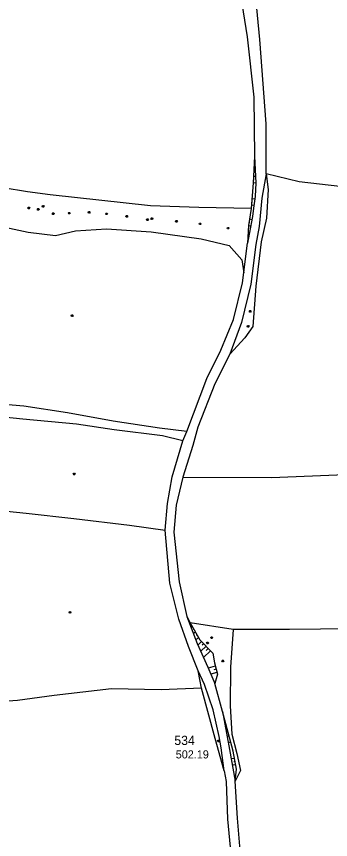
# Model space of a CAD drawing. Extents: x -664960 to -662754, y -993849 to -991145.
# Drawn here: x -663568.6 to -663452.1, y -992520.3 to -992215.3 of the extents above; entities that cross this region are included whole.
import ezdxf

# ---------------------------------------------------------------- set-up
doc = ezdxf.new("R2010")
doc.units = 0
for name, color, linetype in [('Vrstva 1', 7, 'Continuous'), ('Vrstva 13', 7, 'Continuous'), ('Vrstva 27', 7, 'Continuous'), ('Vrstva 63', 7, 'Continuous'), ('Vrstva 8', 7, 'Continuous')]:
    doc.layers.add(name, color=color, linetype=linetype)

msp = doc.modelspace()

# ---------------------------------------------------------------- linework, layer by layer
at = {"layer": 'Vrstva 13'}
for points in [[(-663481.752, -992324.262), (-663481.572, -992324.562), (-663481.752, -992324.862), (-663482.112, -992324.862), (-663482.292, -992324.562), (-663482.112, -992324.262), (-663481.752, -992324.262)], [(-663547.78, -992325.87), (-663547.6, -992326.17), (-663547.78, -992326.47), (-663548.14, -992326.47), (-663548.32, -992326.17), (-663548.14, -992325.87), (-663547.78, -992325.87)], [(-663547.013, -992384.574), (-663546.833, -992384.874), (-663547.013, -992385.174), (-663547.373, -992385.174), (-663547.553, -992384.874), (-663547.373, -992384.574), (-663547.013, -992384.574)], [(-663548.547, -992435.806), (-663548.367, -992436.106), (-663548.547, -992436.406), (-663548.907, -992436.406), (-663549.087, -992436.106), (-663548.907, -992435.806), (-663548.547, -992435.806)], [(-663491.887, -992453.848), (-663491.707, -992454.148), (-663491.887, -992454.448), (-663492.247, -992454.448), (-663492.427, -992454.148), (-663492.247, -992453.848), (-663491.887, -992453.848)]]:
    msp.add_lwpolyline(points, dxfattribs=at)
at = {"layer": 'Vrstva 27'}
for p, q in [((-663498.82, -992462.9), (-663498.82, -992462.9)), ((-663492.21, -992472.91), (-663495.09, -992462.49))]:
    msp.add_line(p, q, dxfattribs=at)
for points in [[(-663475.97, -992273.64), (-663477.58, -992282.65), (-663478.54, -992293.08), (-663479.81, -992299.82), (-663481.67, -992314.53), (-663485.12, -992328.72), (-663489.53, -992340.42), (-663495.04, -992351.42), (-663501.28, -992367.55), (-663503.19, -992374.27), (-663506.96, -992386.03), (-663509.35, -992396.38), (-663510.29, -992406.44), (-663508.31, -992424.82), (-663505.42, -992437.71)], [(-663513.46, -992405.65), (-663512.64, -992395.77), (-663510.85, -992385.96), (-663506.9, -992372.53), (-663505.4, -992369.12), (-663497.96, -992349.47), (-663492.81, -992339.02), (-663488.15, -992327.64), (-663484.78, -992313.98), (-663482.94, -992299.37)], [(-663491.56, -992494.88), (-663492.7, -992486.31), (-663493.48, -992482.18), (-663495.69, -992472.21), (-663498.82, -992462.9), (-663501.24, -992457.75), (-663504.79, -992448.84), (-663508.37, -992438.66), (-663511.74, -992425.37), (-663513.46, -992405.65)], [(-663491.56, -992494.88), (-663490.88, -992498.85), (-663490.29, -992512.79), (-663488.02, -992537.43), (-663486.54, -992563.07), (-663484.58, -992588.12), (-663484.13, -992607.11), (-663484.46, -992622.09), (-663487.97, -992643.83), (-663491.41, -992664.81), (-663493.48, -992685.99), (-663493.6, -992696.61), (-663493.51, -992707.44), (-663493.24, -992730.03), (-663493.3, -992747.16)], [(-663490.38, -992757.18), (-663489.72, -992746.74), (-663489.45, -992730.95), (-663490.22, -992707.23), (-663490.33, -992697.21), (-663489.9, -992685.74), (-663487.82, -992665.56), (-663484.63, -992643.86), (-663480.98, -992622.66), (-663480.17, -992606.94), (-663480.82, -992588.29), (-663482.91, -992562.68), (-663484.55, -992537.62), (-663486.62, -992512.45), (-663487.48, -992498.66)]]:
    msp.add_lwpolyline(points, dxfattribs=at)
at = {"layer": 'Vrstva 63'}
for p, q in [((-663480.569, -992272.068), (-663480.098, -992272.093)), ((-663480.508, -992270.87), (-663480.39, -992270.876)), ((-663480.446, -992269.672), (-663480.207, -992269.684)), ((-663480.692, -992274.465), (-663479.989, -992274.501)), ((-663480.63, -992273.267), (-663480.435, -992273.277)), ((-663480.814, -992276.862), (-663479.88, -992276.91)), ((-663480.753, -992275.664), (-663480.481, -992275.678)), ((-663481.328, -992283.959), (-663481.029, -992283.981)), ((-663481.241, -992282.762), (-663480.262, -992282.833)), ((-663481.415, -992285.156), (-663480.598, -992285.215)), ((-663482.194, -992290.356), (-663481.225, -992290.527)), ((-663482.61, -992292.72), (-663481.682, -992292.883)), ((-663482.402, -992291.538), (-663482.086, -992291.594)), ((-663503.378, -992441.444), (-663503.865, -992441.723)), ((-663502.781, -992442.485), (-663502.996, -992442.608)), ((-663502.185, -992443.526), (-663502.988, -992443.987)), ((-663500.991, -992445.608), (-663502.112, -992446.25)), ((-663501.588, -992444.567), (-663501.908, -992444.751)), ((-663499.966, -992446.941), (-663501.305, -992448.246)), ((-663498.291, -992448.66), (-663500.26, -992450.578)), ((-663499.129, -992447.801), (-663499.679, -992448.337)), ((-663496.617, -992450.38), (-663499.214, -992452.91)), ((-663497.454, -992449.52), (-663498.214, -992450.26)), ((-663494.872, -992456.071), (-663497.487, -992456.779)), ((-663494.245, -992458.388), (-663496.55, -992459.012)), ((-663494.558, -992457.229), (-663495.378, -992457.451)), ((-663495.09, -992462.49), (-663495.09, -992462.49)), ((-663489.729, -992481.889), (-663490.516, -992482.099)), ((-663489.109, -992484.207), (-663490.08, -992484.467)), ((-663489.419, -992483.048), (-663489.712, -992483.126)), ((-663487.735, -992490.245), (-663488.979, -992490.465)), ((-663487.526, -992491.427), (-663487.938, -992491.5)), ((-663487.318, -992492.609), (-663488.547, -992492.826))]:
    msp.add_line(p, q, dxfattribs=at)
for points in [[(-663475.97, -992273.64), (-663476, -992255.14), (-663478.3, -992223.8), (-663480.74, -992199.31), (-663484.94, -992174.65), (-663490.09, -992147.35), (-663493.26, -992125.09), (-663495.9, -992107.68), (-663497.17, -992088.23), (-663498.448, -992067.861)], [(-663503.985, -992068.553), (-663502.49, -992087.58), (-663500.52, -992109.05), (-663498.42, -992128.71), (-663493.79, -992152.11), (-663490.17, -992178.03), (-663483.06, -992222.86), (-663480.63, -992245.25), (-663480.32, -992267.2)], [(-663481.51, -992286.47), (-663501.02, -992286.13), (-663518.86, -992285.48), (-663556.12, -992281.38), (-663564.44, -992280.33), (-663573.46, -992278.84), (-663585.77, -992276.23), (-663602.73, -992270.11), (-663602.69, -992238.93), (-663603.85, -992219.76), (-663605.7, -992189.06), (-663608.17, -992160.04), (-663609.68, -992123.43), (-663609.968, -992095.397)], [(-663480.32, -992267.2), (-663479.88, -992276.91), (-663480.14, -992281.97), (-663480.76, -992286.36), (-663481.02, -992289.47), (-663482.94, -992299.37)], [(-663480.32, -992267.2), (-663480.82, -992276.97), (-663481.51, -992286.47), (-663482.61, -992292.72), (-663482.94, -992299.37)], [(-663475.97, -992273.64), (-663475.23, -992279.48), (-663475.93, -992290.04), (-663477.87, -992298.81), (-663479.89, -992315.2), (-663480.9, -992330.25), (-663483.86, -992334.38), (-663489.53, -992340.42)], [(-663380.29, -992284.44), (-663406.23, -992281.73), (-663425.92, -992279.69), (-663448.69, -992278.31), (-663463.71, -992276.59), (-663475.97, -992273.64)], [(-663563.86, -992286), (-663563.68, -992286.3), (-663563.86, -992286.6), (-663564.22, -992286.6), (-663564.4, -992286.3), (-663564.22, -992286), (-663563.86, -992286)], [(-663560.31, -992286.44), (-663560.13, -992286.74), (-663560.31, -992287.04), (-663560.67, -992287.04), (-663560.85, -992286.74), (-663560.67, -992286.44), (-663560.31, -992286.44)], [(-663558.52, -992285.41), (-663558.34, -992285.71), (-663558.52, -992286.01), (-663558.88, -992286.01), (-663559.06, -992285.71), (-663558.88, -992285.41), (-663558.52, -992285.41)], [(-663541.49, -992287.58), (-663541.31, -992287.88), (-663541.49, -992288.18), (-663541.85, -992288.18), (-663542.03, -992287.88), (-663541.85, -992287.58), (-663541.49, -992287.58)], [(-663594.48, -992289.76), (-663583.4, -992291.17), (-663564.19, -992295.29), (-663554.12, -992296.51), (-663546.74, -992294.7), (-663535.15, -992293.97), (-663518.6, -992295.17), (-663500.08, -992297.7), (-663489.69, -992300.13), (-663485.03, -992305.49), (-663484.316, -992310.298)], [(-663554.75, -992288.05), (-663554.57, -992288.35), (-663554.75, -992288.65), (-663555.11, -992288.65), (-663555.29, -992288.35), (-663555.11, -992288.05), (-663554.75, -992288.05)], [(-663548.85, -992287.9), (-663548.67, -992288.2), (-663548.85, -992288.5), (-663549.21, -992288.5), (-663549.39, -992288.2), (-663549.21, -992287.9), (-663548.85, -992287.9)], [(-663534.98, -992288.15), (-663534.8, -992288.45), (-663534.98, -992288.75), (-663535.34, -992288.75), (-663535.52, -992288.45), (-663535.34, -992288.15), (-663534.98, -992288.15)], [(-663527.49, -992289.03), (-663527.31, -992289.33), (-663527.49, -992289.63), (-663527.85, -992289.63), (-663528.03, -992289.33), (-663527.85, -992289.03), (-663527.49, -992289.03)], [(-663519.85, -992290.35), (-663519.67, -992290.65), (-663519.85, -992290.95), (-663520.21, -992290.95), (-663520.39, -992290.65), (-663520.21, -992290.35), (-663519.85, -992290.35)], [(-663518.17, -992289.89), (-663517.99, -992290.19), (-663518.17, -992290.49), (-663518.53, -992290.49), (-663518.71, -992290.19), (-663518.53, -992289.89), (-663518.17, -992289.89)], [(-663509.08, -992290.94), (-663508.9, -992291.24), (-663509.08, -992291.54), (-663509.44, -992291.54), (-663509.62, -992291.24), (-663509.44, -992290.94), (-663509.08, -992290.94)], [(-663500.31, -992291.86), (-663500.13, -992292.16), (-663500.31, -992292.46), (-663500.67, -992292.46), (-663500.85, -992292.16), (-663500.67, -992291.86), (-663500.31, -992291.86)], [(-663489.92, -992293.46), (-663489.74, -992293.76), (-663489.92, -992294.06), (-663490.28, -992294.06), (-663490.46, -992293.76), (-663490.28, -992293.46), (-663489.92, -992293.46)], [(-663505.4, -992369.12), (-663515.51, -992367.89), (-663532.78, -992365.3), (-663549.69, -992362.2), (-663565.84, -992359.78), (-663577.45, -992358.68), (-663585.93, -992355.61), (-663589.98, -992352.35), (-663592.66, -992338.58), (-663593.9, -992327.81)], [(-663482.51, -992329.89), (-663482.33, -992330.19), (-663482.51, -992330.49), (-663482.87, -992330.49), (-663483.05, -992330.19), (-663482.87, -992329.89), (-663482.51, -992329.89)], [(-663506.9, -992372.53), (-663514.48, -992370.71), (-663532.3, -992368.45), (-663546.28, -992366.4), (-663566.18, -992364.53), (-663580.66, -992363.02), (-663580.98, -992375.32), (-663582.04, -992387.99), (-663583.06, -992397.54)], [(-663506.96, -992386.03), (-663473.97, -992386.18), (-663440.6, -992384.86), (-663412.71, -992382.62), (-663383.01, -992378.86), (-663352.92, -992373.77), (-663328.49, -992369.51), (-663324.56, -992381.56), (-663321.02, -992394.46), (-663312.91, -992423.04), (-663327.66, -992426.41), (-663351.95, -992431.22), (-663383.52, -992436.14), (-663417.4, -992440.81), (-663444.41, -992442.2), (-663467.36, -992442.46), (-663488.2, -992442.47), (-663504.16, -992440.08)], [(-663499.92, -992464.28), (-663514.94, -992464.83), (-663533.36, -992464.54), (-663554.56, -992466.98), (-663568.21, -992468.77), (-663587.82, -992470.16), (-663586.82, -992445.55), (-663585.9, -992426.57), (-663584.43, -992407.82), (-663583.06, -992397.54), (-663564.96, -992399.36), (-663547.32, -992401.35), (-663526.65, -992403.83), (-663513.46, -992405.65)], [(-663505.42, -992437.71), (-663504.16, -992440.08), (-663500.6, -992446.29), (-663495.72, -992451.3), (-663495.2, -992454.86), (-663494.06, -992459.07), (-663495.09, -992462.49)], [(-663505.42, -992437.71), (-663501.55, -992447.7), (-663497.6, -992456.51), (-663495.09, -992462.49)], [(-663488.2, -992442.47), (-663489.23, -992456.44), (-663489.35, -992470.74), (-663488.72, -992481.33), (-663486.86, -992488.47), (-663485.5, -992494.73), (-663487.48, -992498.66)], [(-663496.02, -992445.19), (-663495.84, -992445.49), (-663496.02, -992445.79), (-663496.38, -992445.79), (-663496.56, -992445.49), (-663496.38, -992445.19), (-663496.02, -992445.19)], [(-663497.56, -992447.21), (-663497.38, -992447.51), (-663497.56, -992447.81), (-663497.92, -992447.81), (-663498.1, -992447.51), (-663497.92, -992447.21), (-663497.56, -992447.21)], [(-663491.56, -992494.88), (-663494.96, -992482.9), (-663499.92, -992464.28), (-663501.24, -992457.75)], [(-663487.48, -992498.66), (-663487.03, -992494.24), (-663488.2, -992487.61), (-663490.06, -992480.65), (-663492.21, -992472.91)], [(-663492.21, -992472.91), (-663489.62, -992486.96), (-663487.48, -992498.66)]]:
    msp.add_lwpolyline(points, dxfattribs=at)
at = {"layer": 'Vrstva 8'}
msp.add_lwpolyline([(-663493.49, -992483.53), (-663493.31, -992483.83), (-663493.49, -992484.13), (-663493.85, -992484.13), (-663494.03, -992483.83), (-663493.85, -992483.53), (-663493.49, -992483.53)], dxfattribs=at)

# ---------------------------------------------------------------- texts
at = {"layer": 'Vrstva 1'}
msp.add_text('534', height=3.4, dxfattribs=at).set_placement((-663510.054, -992485.297))
at = {"layer": 'Vrstva 63'}
msp.add_text('502.19', height=3, dxfattribs=at).set_placement((-663509.53, -992490.277))

doc.saveas('drawing.dxf')
